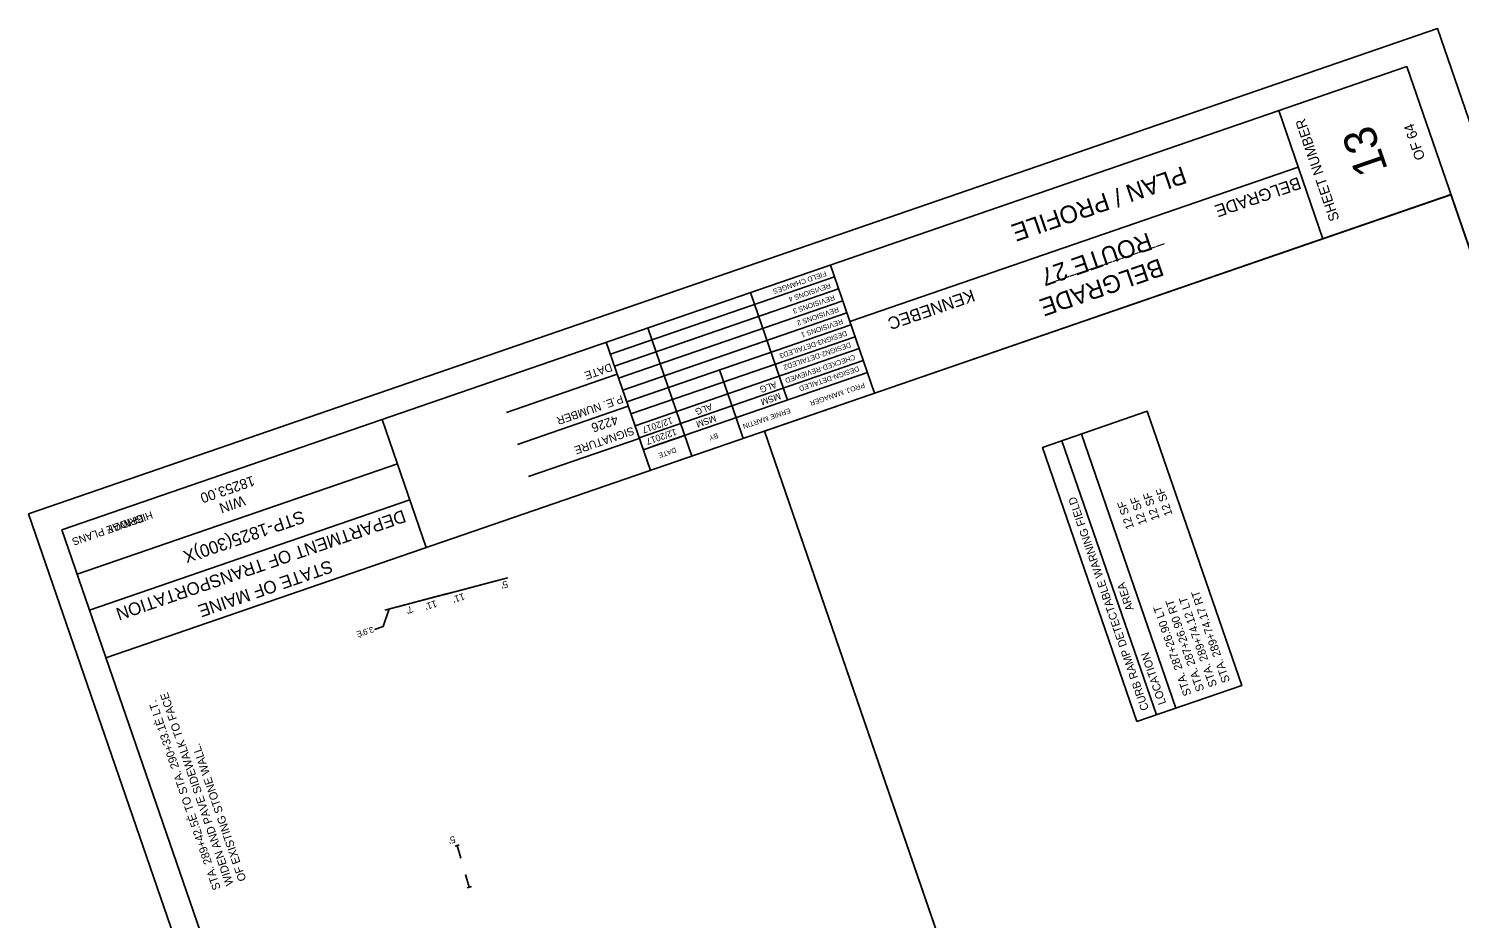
# Model space of a CAD drawing. Extents: x 1111039 to 1111836, y 617707 to 618690.
# Drawn here: x 1111039 to 1111567, y 618362 to 618690 of the extents above; entities that cross this region are included whole.
import ezdxf

# ---------------------------------------------------------------- set-up
doc = ezdxf.new("R2010")
doc.units = 0
for name, color, linetype in [('H_V ANNOTATION', 7, 'Continuous'), ('MINOR', 7, 'Continuous'), ('S_Roadway_Centerline', 7, 'Continuous'), ('S_Roadway_Sidewalks_Paved', 7, 'Continuous'), ('S_Utilities_GuyWire3', 7, 'Continuous'), ('SHADING', 7, 'Continuous')]:
    doc.layers.add(name, color=color, linetype=linetype)

msp = doc.modelspace()

# ---------------------------------------------------------------- linework, layer by layer
at = {"layer": 'MINOR'}
for p, q in [((1111547.51, 618675.96), (1111051.11, 618505.04)), ((1111807.98, 617919.56), (1111547.52, 618675.97)), ((1111516.51, 618612.41), (1111500.23, 618659.69)), ((1111507.41, 618638.84), (1111341.94, 618581.87)), ((1111563.79, 618628.69), (1111067.39, 618457.77)), ((1111351.05, 618555.44), (1111334.77, 618602.71)), ((1111268.31, 618526.95), (1111252.03, 618574.22)), ((1111256.1, 618562.41), (1111215.22, 618548.33)), ((1111260.17, 618550.59), (1111219.29, 618536.51)), ((1111185.62, 618498.48), (1111169.34, 618545.75)), ((1111264.24, 618538.77), (1111223.36, 618524.69)), ((1111554.58, 617832.3), (1111310.4, 618541.44)), ((1111174.99, 618529.31), (1111056.8, 618488.62)), ((1111179.54, 618516.1), (1111061.35, 618475.4)), ((1111051.13, 618505.05), (1111311.58, 617748.63))]:
    msp.add_line(p, q, dxfattribs=at)
for points in [[(1111336.27, 618598.31), (1111253.55, 618569.82)], [(1111337.78, 618593.9), (1111255.07, 618565.42)], [(1111339.3, 618589.5), (1111256.58, 618561.02)], [(1111318.87, 618552.9), (1111305.22, 618592.54)], [(1111340.82, 618585.09), (1111258.1, 618556.61)], [(1111342.33, 618580.69), (1111259.62, 618552.21)], [(1111283.68, 618532.24), (1111267.4, 618579.52)], [(1111343.85, 618576.28), (1111261.13, 618547.8)], [(1111262.65, 618543.4), (1111345.37, 618571.88)], [(1111346.88, 618567.47), (1111264.17, 618538.99)], [(1111348.4, 618563.07), (1111269.02, 618535.74)], [(1111299.96, 618546.39), (1111293.89, 618564)], [(1111302.59, 618538.75), (1111299.96, 618546.39)], [(1111281.05, 618539.87), (1111265.68, 618534.58)]]:
    msp.add_lwpolyline(points, dxfattribs=at)
at = {"layer": 'S_Roadway_Sidewalks_Paved'}
msp.add_lwpolyline([(1111835.61, 617886.27), (1111558.88, 618689.96), (1111038.85, 618510.9), (1111315.58, 617707.21)], close=True, dxfattribs=at)
at = {"layer": 'S_Utilities_GuyWire3'}
for p, q in [((1111455.06, 618436.7), (1111420.22, 618537.9)), ((1111462.23, 618439.16), (1111427.38, 618540.37)), ((1111192.48, 618481.21), (1111203.12, 618484.01)), ((1111203.15, 618484.02), (1111192.52, 618481.22)), ((1111200.22, 618483.25), (1111210.86, 618486.05)), ((1111213.76, 618486.82), (1111203.12, 618484.01)), ((1111171.21, 618475.61), (1111181.85, 618478.41)), ((1111185.73, 618479.43), (1111175.09, 618476.63)), ((1111192.48, 618481.21), (1111181.85, 618478.41)), ((1111181.88, 618478.42), (1111192.52, 618481.22)), ((1111197.78, 618388.75), (1111196.25, 618388.3)), ((1111198.31, 618383.85), (1111196.96, 618388.51)), ((1111200.08, 618377.79), (1111201.43, 618373.14)), ((1111202.25, 618373.38), (1111200.72, 618372.93))]:
    msp.add_line(p, q, dxfattribs=at)
msp.add_lwpolyline([(1111447.9, 618434.23), (1111413.05, 618535.43), (1111451.73, 618548.75), (1111486.58, 618447.55)], close=True, dxfattribs=at)
for points in [[(1111170.34, 618475.38), (1111215.7, 618487.33)], [(1111166.52, 618468.24), (1111169.75, 618469.36), (1111171.94, 618475.8)]]:
    msp.add_lwpolyline(points, dxfattribs=at)
at = {"layer": 'SHADING'}
msp.add_lwpolyline([(1111807.98, 617919.56), (1111563.8, 618628.7), (1111310.4, 618541.44), (1111554.58, 617832.3)], close=True, dxfattribs=at)

# ---------------------------------------------------------------- texts
at = {"layer": 'H_V ANNOTATION'}
for s, height, p in [('BELGRADE', 4.536, (1111507.46, 618635.31)), ('_____________', 4.5358, (1111458.34, 618609.53)), ('KENNEBEC', 4.536, (1111387.07, 618593.86)), ('BRIDGE PLANS', 2.795, (1111080.75, 618510.79))]:
    msp.add_text(s, height=height, rotation=199, dxfattribs=at).set_placement(p)
at = {"layer": 'MINOR'}
for s, height, rotation, p in [('SHEET NUMBER', 3.7264, 109, (1111522.68, 618619.64)), ('13', 12.097, 109, (1111540.59, 618638)), ('OF 64', 3.726, 109, (1111554.33, 618642.18)), ('PLAN / PROFILE', 6.5214, 199, (1111464.72, 618639.34)), ('FIELD CHANGES', 1.8637, 199, (1111332.94, 618600.51)), ('REVISIONS 4', 1.8637, 199, (1111334.46, 618596.11)), ('REVISIONS 3', 1.8637, 199, (1111335.98, 618591.7)), ('REVISIONS 2', 1.8637, 199, (1111337.49, 618587.3)), ('REVISIONS 1', 1.8637, 199, (1111339.01, 618582.89)), ('DESIGN3-DETAILED3', 1.8637, 199, (1111340.53, 618578.49)), ('DESIGN2-DETAILED2', 1.8637, 199, (1111341.98, 618574.26)), ('CHECKED-REVIEWED', 1.8637, 199, (1111343.56, 618569.68)), ('DATE', 2.953, 199, (1111253.66, 618566.54)), ('DESIGN-DETAILED', 1.8637, 199, (1111345.02, 618565.45)), ('ALG', 2.423, 199, (1111314.5, 618559.86)), ('PROJ. MANAGER', 1.8637, 199, (1111347.1, 618559.39)), ('P.E. NUMBER', 2.9528, 199, (1111257.7, 618554.82)), ('MSM', 2.423, 199, (1111315.95, 618555.64)), ('ALG', 2.423, 199, (1111290.66, 618551.66)), ('MSM', 2.423, 199, (1111292.11, 618547.43)), ('ERNIE MARTIN', 1.8637, 199, (1111319.67, 618549.94)), ('SIGNATURE', 2.953, 199, (1111261.74, 618543.09)), ('12/2017', 2.423, 199, (1111276.08, 618546.64)), ('12/2017', 2.423, 199, (1111277.54, 618542.41)), ('BY', 1.857, 199, (1111292.99, 618540.76)), ('DATE', 1.857, 199, (1111277.52, 618535.43)), ('18253.00', 3.726, 199, (1111121.52, 618525.03)), ('WIN', 3.726, 199, (1111118, 618517.69)), ('DEPARTMENT OF TRANSPORTATION', 4.6588, 199, (1111177.04, 618512.48)), ('STP-1825(300)X', 4.6588, 199, (1111139.75, 618512.25)), ('STATE OF MAINE', 4.6588, 199, (1111150.08, 618493.93))]:
    msp.add_text(s, height=height, rotation=rotation, dxfattribs=at).set_placement(p)
at = {"layer": 'S_Roadway_Centerline'}
for s, height, p in [('ROUTE 27', 6.521, (1111452.05, 618614.85)), ('BELGRADE', 6.521, (1111456.28, 618605.27)), ('HIGHWAY PLANS', 2.795, (1111084.1, 618511.95))]:
    msp.add_text(s, height=height, rotation=199, dxfattribs=at).set_placement(p)
at = {"layer": 'S_Utilities_GuyWire3'}
for s, height, rotation, p in [('4226', 3.396, 199, (1111255.73, 618547.36)), ('CURB RAMP DETECTABLE WARNING FIELD', 2.9531, 109, (1111452.35, 618438.88)), ('12 SF', 3.006, 109, (1111446.89, 618505.81)), ('12 SF', 3.006, 109, (1111451.63, 618507.44)), ('12 SF', 3.006, 109, (1111456.36, 618509.07)), ('12 SF', 3.006, 109, (1111461.1, 618510.7)), ("5'", 2.55, 196.7201, (1111215.3, 618486.38)), ('LOCATION               AREA', 2.9531, 109, (1111458.71, 618441.07)), ("11'", 2.55, 197.9467, (1111189.09, 618479.08)), ("11'", 2.55, 197.9467, (1111199.34, 618481.72)), ('STA. 287+26.90 RT', 3.0059, 109, (1111472.81, 618445.93)), ('STA. 289+74.12 LT', 3.0059, 109, (1111477.54, 618447.56)), ('STA. 289+74.17 RT', 3.0059, 109, (1111482.28, 618449.19)), ("7'", 2.55, 203.4722, (1111180.07, 618477.16)), ('STA. 287+26.90 LT', 3.0059, 109, (1111468.07, 618444.29)), ("3.9'È", 2.167, 197.5618, (1111165.82, 618469.38)), ('STA. 289+42.5È TO STA. 290+33.1È LT.', 3, 108.9493, (1111109.81, 618372.65)), ('WIDEN AND PAVE SIDEWALK TO FACE', 3, 108.9493, (1111114.53, 618374.28)), ('OF EXISTING STONE WALL.', 3, 108.9493, (1111119.26, 618375.9)), ("5'", 2.55, 196.7201, (1111195.92, 618392.13))]:
    msp.add_text(s, height=height, rotation=rotation, dxfattribs=at).set_placement(p)

doc.saveas('drawing.dxf')
